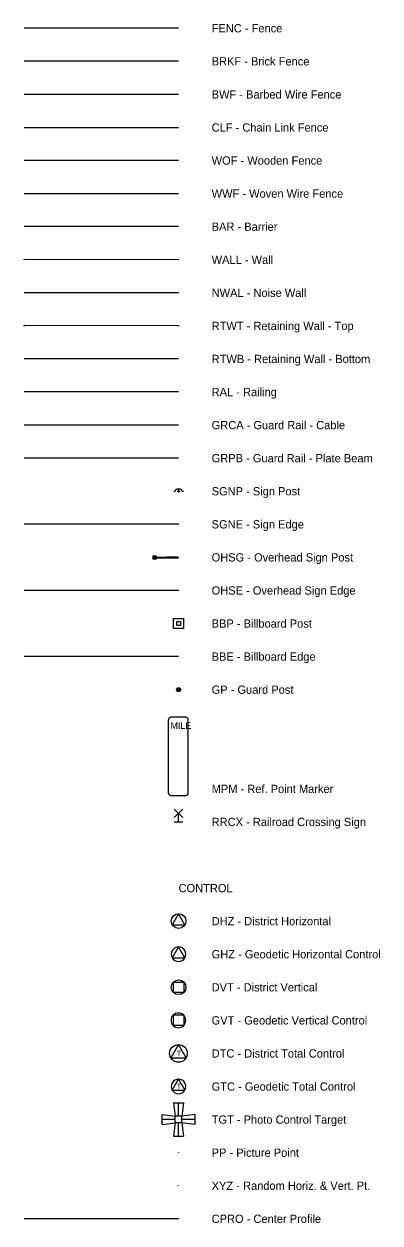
# Model space of a CAD drawing. Extents: x 2147716 to 2176321, y 2125040 to 2131750.
# Drawn here: x 2175978 to 2176301, y 2128234 to 2129322 of the extents above; entities that cross this region are included whole.
import ezdxf

# ---------------------------------------------------------------- set-up
doc = ezdxf.new("R2010")
doc.units = 0
for name, color, linetype in [('Default', 7, 'Continuous'), ('HORZ CTRL', 7, 'Continuous'), ('MANMD STRU INP', 7, 'Continuous'), ('PHO CTRL', 7, 'Continuous'), ('PNM MNMD STRU INP', 7, 'Continuous'), ('VERT CTRL', 7, 'Continuous')]:
    doc.layers.add(name, color=color, linetype=linetype)

msp = doc.modelspace()

# ---------------------------------------------------------------- linework, layer by layer
at = {"layer": 'HORZ CTRL'}
for p, q in [((2176118.6, 2128514.7), (2176112.8, 2128504.7)), ((2176124.4, 2128504.7), (2176118.6, 2128514.7)), ((2176112.8, 2128504.7), (2176124.4, 2128504.7)), ((2176118.6, 2128508), (2176118.6, 2128508)), ((2176118.6, 2128508), (2176118.6, 2128508)), ((2176118.6, 2128508), (2176118.6, 2128508)), ((2176118.6, 2128478), (2176118.6, 2128478)), ((2176118.6, 2128478), (2176118.6, 2128478)), ((2176118.6, 2128478), (2176118.6, 2128478)), ((2176118.5, 2128396.1), (2176111.6, 2128384.1)), ((2176125.5, 2128384.1), (2176118.5, 2128396.1)), ((2176111.6, 2128384.1), (2176125.5, 2128384.1)), ((2176118.5, 2128388), (2176118.5, 2128388)), ((2176118.5, 2128388), (2176118.5, 2128388)), ((2176118.5, 2128388), (2176118.5, 2128388)), ((2176118.6, 2128358), (2176118.6, 2128358)), ((2176118.6, 2128358), (2176118.6, 2128358)), ((2176118.6, 2128358), (2176118.6, 2128358))]:
    msp.add_line(p, q, dxfattribs=at)
for points in [[(2176118.6, 2128484.7), (2176112.8, 2128474.7)], [(2176124.4, 2128474.7), (2176118.6, 2128484.7)], [(2176112.8, 2128474.7), (2176124.4, 2128474.7)], [(2176112.8, 2128354.7), (2176118.6, 2128364.7)], [(2176118.6, 2128364.7), (2176124.4, 2128354.7)], [(2176112.8, 2128354.7), (2176124.4, 2128354.7)]]:
    msp.add_lwpolyline(points, dxfattribs=at)
for centre, radius in [((2176118.6, 2128508), 6.67), ((2176118.5, 2128388), 8)]:
    msp.add_circle(centre, radius, dxfattribs=at)
for centre, radius, start, end in [((2176118.8, 2128477.9), 6.78, 91.4546, 208.318), ((2176118.4, 2128477.9), 6.81, 332.0572, 88.1702), ((2176118.6, 2128478.2), 6.79, 211.3182, 328.6818), ((2176118.8, 2128357.9), 6.78, 91.4546, 208.318), ((2176118.4, 2128357.9), 6.81, 332.0572, 88.1702), ((2176118.6, 2128358.2), 6.79, 211.3182, 328.6818)]:
    msp.add_arc(centre, radius, start, end, dxfattribs=at)
at = {"layer": 'MANMD STRU INP'}
for p, q in [((2176118.6, 2129318), (2175978.6, 2129318)), ((2176118.6, 2129288), (2175978.6, 2129288)), ((2176118.6, 2129258), (2175978.6, 2129258)), ((2175978.6, 2129228), (2176118.6, 2129228)), ((2176118.6, 2129198), (2175978.6, 2129198)), ((2175978.6, 2129168), (2176118.6, 2129168)), ((2176118.6, 2129138), (2175978.6, 2129138)), ((2176118.6, 2129108), (2175978.7, 2129108.2)), ((2176118.6, 2129078), (2175978.7, 2129078)), ((2176118.6, 2129048), (2175978.6, 2129048.2)), ((2176118.6, 2129018), (2175978.8, 2129018)), ((2176118.6, 2128988), (2175978.6, 2128988)), ((2176118.6, 2128958), (2175978.6, 2128958)), ((2176118.6, 2128928), (2175978.6, 2128928)), ((2176114.2, 2128898), (2176115.6, 2128898)), ((2176115.6, 2128898), (2176116.6, 2128900.1)), ((2176116.6, 2128900.1), (2176120.7, 2128900.1)), ((2176117.4, 2128898), (2176118.6, 2128898)), ((2176118.6, 2128899.3), (2176118.6, 2128898)), ((2176118.6, 2128898), (2176118.6, 2128896.7)), ((2176118.6, 2128898), (2176119.8, 2128898)), ((2176120.7, 2128900.1), (2176121.6, 2128898)), ((2176121.6, 2128898), (2176123, 2128898)), ((2176118.6, 2128868), (2175978.6, 2128868)), ((2176118.5, 2128867.8), (2176118.7, 2128868.2)), ((2176118.5, 2128868.2), (2176118.7, 2128867.8)), ((2176095.2, 2128839.3), (2176095.2, 2128836.3)), ((2176095.2, 2128839.3), (2176098.2, 2128839.3)), ((2176098.2, 2128839.3), (2176098.2, 2128836.3)), ((2176098.2, 2128836.3), (2176095.2, 2128836.3)), ((2176096.7, 2128838.1), (2176118.3, 2128838.1)), ((2176096.7, 2128837.8), (2176096.7, 2128837.8)), ((2176096.7, 2128837.5), (2176118.3, 2128837.5)), ((2176107.8, 2128838.4), (2176118.3, 2128838.4)), ((2176118.3, 2128838.1), (2176118.3, 2128837.5)), ((2176118.6, 2128808), (2175978.6, 2128808)), ((2176118.5, 2128807.8), (2176118.7, 2128808.2)), ((2176118.5, 2128808.2), (2176118.7, 2128807.8)), ((2176118.6, 2128778), (2176118.6, 2128778)), ((2176118.6, 2128778), (2176118.6, 2128778)), ((2176118.6, 2128748), (2175978.6, 2128748)), ((2176109.3, 2128690.6), (2176109.3, 2128624.2)), ((2176125.1, 2128692.9), (2176111.6, 2128692.9)), ((2176127.3, 2128624.2), (2176127.3, 2128690.6)), ((2176111.6, 2128621.9), (2176125.1, 2128621.9)), ((2176114.7, 2128609.4), (2176122.5, 2128601.9)), ((2176114.7, 2128601.9), (2176122.5, 2128609.4)), ((2176118.6, 2128598), (2176118.6, 2128605.5)), ((2176114.7, 2128598), (2176122.5, 2128598))]:
    msp.add_line(p, q, dxfattribs=at)
for points in [[(2176114.1, 2128773.4), (2176114.1, 2128782.5), (2176123.2, 2128782.5), (2176123.2, 2128773.4)], [(2176116.9, 2128776.2), (2176116.9, 2128779.7), (2176120.4, 2128779.7), (2176120.4, 2128776.2)]]:
    msp.add_lwpolyline(points, close=True, dxfattribs=at)
for centre, radius in [((2176096.7, 2128837.8), 1.2), ((2176096.7, 2128837.8), 0.3), ((2176118.6, 2128718), 1.83), ((2176118.6, 2128718), 1.35), ((2176118.6, 2128718), 0.794)]:
    msp.add_circle(centre, radius, dxfattribs=at)
for centre, start, end in [((2176111.6, 2128690.6), 90, 180), ((2176125.1, 2128690.6), 0, 90), ((2176111.6, 2128624.2), 180, 270), ((2176125.1, 2128624.2), 270, 0)]:
    msp.add_arc(centre, 2.25, start, end, dxfattribs=at)
at = {"layer": 'PHO CTRL'}
for p, q in [((2176114.1, 2128343), (2176118.6, 2128343)), ((2176114.1, 2128343), (2176115.6, 2128331)), ((2176118.6, 2128331), (2176118.6, 2128343)), ((2176118.6, 2128343), (2176123.1, 2128343)), ((2176123.1, 2128343), (2176121.6, 2128331)), ((2176103.6, 2128328), (2176103.6, 2128332.5)), ((2176103.6, 2128332.5), (2176115.6, 2128331)), ((2176103.6, 2128323.5), (2176103.6, 2128328)), ((2176115.6, 2128328), (2176103.6, 2128328)), ((2176115.6, 2128328), (2176115.6, 2128331)), ((2176121.6, 2128331), (2176115.6, 2128331)), ((2176115.6, 2128325), (2176115.6, 2128328)), ((2176118.6, 2128328), (2176118.6, 2128328)), ((2176133.6, 2128332.5), (2176121.6, 2128331)), ((2176121.6, 2128328), (2176121.6, 2128331)), ((2176121.6, 2128325), (2176121.6, 2128328)), ((2176133.6, 2128328), (2176121.6, 2128328)), ((2176133.6, 2128328), (2176133.6, 2128332.5)), ((2176133.6, 2128323.5), (2176133.6, 2128328)), ((2176103.6, 2128323.5), (2176115.6, 2128325)), ((2176115.6, 2128325), (2176114.1, 2128313)), ((2176121.6, 2128325), (2176115.6, 2128325)), ((2176118.6, 2128313), (2176118.6, 2128325)), ((2176133.6, 2128323.5), (2176121.6, 2128325)), ((2176121.6, 2128325), (2176123.1, 2128313)), ((2176114.1, 2128313), (2176118.6, 2128313)), ((2176118.6, 2128313), (2176123.1, 2128313)), ((2176118.5, 2128297.8), (2176118.7, 2128298.2)), ((2176118.5, 2128298.2), (2176118.7, 2128297.8)), ((2176118.5, 2128267.8), (2176118.7, 2128268.2)), ((2176118.5, 2128268.2), (2176118.7, 2128267.8)), ((2176118.6, 2128238), (2175978.6, 2128238)), ((2176118.5, 2128237.8), (2176118.7, 2128238.2)), ((2176118.5, 2128238.2), (2176118.7, 2128237.8))]:
    msp.add_line(p, q, dxfattribs=at)
at = {"layer": 'PNM MNMD STRU INP'}
for p, q in [((2175978.5, 2129107.8), (2175978.7, 2129108.2)), ((2175978.5, 2129108.2), (2175978.7, 2129107.8)), ((2176118.5, 2129107.8), (2176118.7, 2129108.2)), ((2176118.5, 2129108.2), (2176118.7, 2129107.8)), ((2176118.5, 2129077.8), (2176118.7, 2129078.2)), ((2176118.5, 2129078.2), (2176118.7, 2129077.8)), ((2175978.6, 2129047.8), (2175978.8, 2129048.2)), ((2175978.6, 2129048.2), (2175978.8, 2129047.8)), ((2176118.5, 2129047.8), (2176118.7, 2129048.2)), ((2176118.5, 2129048.2), (2176118.7, 2129047.8))]:
    msp.add_line(p, q, dxfattribs=at)
at = {"layer": 'VERT CTRL'}
for p, q in [((2176118.6, 2128448), (2176118.6, 2128448)), ((2176118.6, 2128448), (2176118.6, 2128448)), ((2176118.6, 2128418), (2176118.6, 2128418)), ((2176118.6, 2128418), (2176118.6, 2128418))]:
    msp.add_line(p, q, dxfattribs=at)
msp.add_lwpolyline([(2176113.9, 2128443.3), (2176113.9, 2128452.7), (2176123.3, 2128452.7), (2176123.3, 2128443.3)], close=True, dxfattribs=at)
for points in [[(2176123.3, 2128422.7), (2176113.8, 2128422.7)], [(2176113.8, 2128422.7), (2176113.8, 2128413.3)], [(2176123.3, 2128422.7), (2176123.3, 2128422.7)], [(2176123.3, 2128422.7), (2176123.3, 2128413.3)], [(2176123.3, 2128413.3), (2176113.8, 2128413.3)]]:
    msp.add_lwpolyline(points, dxfattribs=at)
msp.add_circle((2176118.6, 2128448), 6.67, dxfattribs=at)
for centre, radius, start, end in [((2176118.6, 2128418), 6.74, 135.7573, 224.2427), ((2176118.5, 2128417.8), 6.82, 45.8526, 134.1474), ((2176118.3, 2128418), 6.85, 316.6405, 43.3595), ((2176118.5, 2128418.2), 6.87, 226.2206, 313.7794)]:
    msp.add_arc(centre, radius, start, end, dxfattribs=at)

# ---------------------------------------------------------------- texts
at = {"layer": 'Default'}
for s, p in [('FENC - Fence', (2176148.6, 2129314.2)), ('BRKF - Brick Fence', (2176148.6, 2129284.2)), ('BWF - Barbed Wire Fence', (2176148.6, 2129254.2)), ('CLF - Chain Link Fence', (2176148.6, 2129224.2)), ('WOF - Wooden Fence', (2176148.6, 2129194.2)), ('WWF - Woven Wire Fence', (2176148.6, 2129164.2)), ('BAR - Barrier', (2176148.6, 2129134.2)), ('WALL - Wall', (2176148.6, 2129104.2)), ('NWAL - Noise Wall', (2176148.6, 2129074.2)), ('RTWT - Retaining Wall - Top', (2176148.6, 2129044.2)), ('RTWB - Retaining Wall - Bottom', (2176148.6, 2129014.2)), ('RAL - Railing', (2176148.6, 2128984.2)), ('GRCA - Guard Rail - Cable', (2176148.6, 2128954.2)), ('GRPB - Guard Rail - Plate Beam', (2176148.6, 2128924.2)), ('SGNP - Sign Post', (2176148.6, 2128894.2)), ('SGNE - Sign Edge', (2176148.6, 2128864.2)), ('OHSG - Overhead Sign Post', (2176148.6, 2128834.2)), ('OHSE - Overhead Sign Edge', (2176148.6, 2128804.2)), ('BBP - Billboard Post', (2176148.6, 2128774.2)), ('BBE - Billboard Edge', (2176148.6, 2128744.2)), ('GP - Guard Post', (2176148.6, 2128714.2)), ('MPM - Ref. Point Marker', (2176148.6, 2128624.2)), ('RRCX - Railroad Crossing Sign', (2176148.6, 2128594.2)), ('CONTROL', (2176118.6, 2128534.2)), ('DHZ - District Horizontal', (2176148.6, 2128504.2)), ('GHZ - Geodetic Horizontal Control', (2176148.6, 2128474.2)), ('DVT - District Vertical', (2176148.6, 2128444.2)), ('GVT - Geodetic Vertical Control', (2176148.6, 2128414.2)), ('DTC - District Total Control', (2176148.6, 2128384.2)), ('GTC - Geodetic Total Control', (2176148.6, 2128354.2)), ('TGT - Photo Control Target', (2176148.6, 2128324.2)), ('PP - Picture Point', (2176148.6, 2128294.2)), ('XYZ - Random Horiz. & Vert. Pt.', (2176148.6, 2128264.2)), ('CPRO - Center Profile', (2176148.6, 2128234.2))]:
    msp.add_text(s, height=7.5, dxfattribs=at).set_placement(p)
at = {"layer": 'HORZ CTRL'}
for p in [(2176117, 2128385.5), (2176117, 2128355.5)]:
    msp.add_text('T', height=5, dxfattribs=at).set_placement(p)
at = {"layer": 'MANMD STRU INP'}
msp.add_text('MILE', height=6.03, dxfattribs=at).set_placement((2176111.3, 2128682.4))

doc.saveas('drawing.dxf')
